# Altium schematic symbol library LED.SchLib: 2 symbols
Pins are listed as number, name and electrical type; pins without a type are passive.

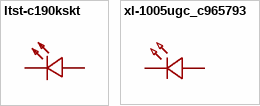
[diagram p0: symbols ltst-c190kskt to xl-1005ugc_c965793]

## ltst-c190kskt
designator LED??  (value not drawn)
灯头类型:-;发光颜色:黄色;正向压降(Vf):2.1V;功率:75mW;正向电流:20mA;波长:584.5nm~597nm;二极管配置:独立二极管;透镜颜色:无色透明透镜;色温:-;发光强度:104mcd;发光角度:130°;载带方式:-;工作温度:-30℃~+85℃;; Manufacturer: LITEON(光宝); AddInBom: yes; ModelId: 1f0d29a91be547639d425604e9b96ebb; ModelName: LED0603-RD; ModelTransform: 63.7794,32.283,0,0,0,0,0,0,0; Illumination Color: 黄色; Voltage - Forward(Vf): 2.1V; Power(Watts): 75mW; Forward Current: 20mA; Peak Wavelength: 588nm; Diode Configuration: 独立二极管; Lens Color: 无色透明透镜; Luminous Intensity: 104mcd; Viewing Angle: 130°
footprint LED0603-RD
pins: 1 -, 2 +

## xl-1005ugc_c965793
designator LED??  (value not drawn)
灯头类型:1.0mmx0.5mm方形灯头;发光颜色:翠绿色;正向压降(Vf):3V;功率:80mW;正向电流:25mA;波长:516nm~531nm;二极管配置:独立二极管;透镜颜色:无色透明透镜;色温:-;发光强度:249mcd;发光角度:120°;载带方式:正贴;工作温度:-40℃~+85℃;; Manufacturer: XINGLIGHT(成兴光); AddInBom: yes; ModelId: 080bb9bd520f4b34ac21e218e7b036d6; ModelName: LED0402_L1.0-W0.5-H0.2; ModelTransform: 40.1574,19.685,0,0,0,0,0,-0.0005,0; Illumination Color: 翠绿色; Voltage - Forward(Vf): 3V; Power(Watts): 80mW; Forward Current: 25mA; Peak Wavelength: 531nm; Diode Configuration: 独立二极管; Lens Color: 无色透明透镜; Luminous Intensity: 249mcd; Viewing Angle: 120°
footprint LED0402-RD_GREEN
pins: 1 K, 2 A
